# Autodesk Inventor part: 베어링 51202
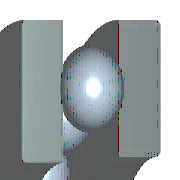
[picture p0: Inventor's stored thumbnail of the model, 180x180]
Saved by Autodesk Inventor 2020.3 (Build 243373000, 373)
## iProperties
Created: 2012-02
Part Number: 베어링 51202
Material: 강철, 연강
Description: 롤링 베어링 - 플랫 뒷면이 있는 스러스트 볼 베어링
Document SubType Name: Modeling
Standard: KS B 2022
Designer: mduedu
Standards Organization: KS
Language: ko-KR
Size Designation: 51202 - 15 x 32 x 12
Categories: <MemberInstance><Categories><Category DisplayName="샤프트 부품" InternalName="7f7aeb1f-a693-4053-b835-cee3144e0d98" Mnemonic="SHFT"><Category DisplayName="베어링" Inter
Density: 1 g/cm^3
Appearance: 진녹색
IsCustomPart: 1
Author: mduedu
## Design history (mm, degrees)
sketch "스케치1" dims "d3" = 5.28 (= 0.44 x KB)
  geometry: L1 (6, 9.61)-(6, 14.89); L2 (8.64, 12.25)-(3.36, 12.25); L3 (3.6, 16)-(0, 16); L4 (3.6, 7.5)-(0, 7.5); L5 (8.4, 13.35)-(8.4, 16); L6 (8.4, 16)-(12, 16); L7 (12, 16)-(12, 8.5); L8 (12, 8.5)-(8.4, 8.5); L9 (8.4, 8.5)-(8.4, 11.15); L10 (3.6, 16)-(3.6, 13.35); L11 (3.6, 11.15)-(3.6, 7.5); L12 (-1.8, 0)-(10.8, 0) reference; L13 (0, -0.022)-(0, 5.522) reference; 1 further point
  constraints: 22 end point, 5 perpendicular, 2 equal length, 2 midpoint, 2 parallel, 2 point on line, 1 collinear, 10 other
  dimensions: "d8" = 4.8 diameter of L11 L1 (= 0.4 x KB); "d11" = 15 diameter of L4 L12 (= WD); "d12" = 17 diameter of L8 L12 (= KAD1); "d13" = 32 diameter of L3 L12 (= KID1); "d14" = 32 diameter of L6 L12 (= BD); "d15" = 24.5 diameter of point (6, 12.25) L12 (= 0.5 x KID1 + 0.5 x KAD1); "d16" = 6 distance from line of point (6, 12.25) L13 (= 0.5 x KB); "d18" = 12 distance between parallel lines of L7 L13 (= KB)
revolve "본체" stored, may be unused: angle "d9" = 90 deg
revolve "볼" stored, may be unused: angle "d10" = 90 deg
pattern_circular "IDS_ARRAYBALL[SIMPL:T]" dims angle "d2" = 360 deg
body "Solid1"
fillet "모깎기1" dims "d4" = 0.6 (= KRS)
fillet "모깎기2" dims "d5" = 0.6 (= KRS)
other parameters: "WD" = 15 [user parameter; used in 2 equation terms], "KAD1" = 17 [user parameter; used in 3 equation terms], "KID1" = 32 [user parameter; used in 3 equation terms], "BD" = 32 [user parameter; used in 2 equation terms], "KB" = 12 [user parameter; used in 6 equation terms], "KRS" = 0.6 [user parameter; used in 2 equation terms], "d0" = 2.4 (= 0.2 x KB), "d6" = 0, "d7" = 0, "d19" = 0, "d41" = 0, "d42" = 0, "WR" = 7.5 (= 0.5 x WD) [user parameter], "BC" = 1.65e+07 [user parameter], "BBA" = 90 deg [user parameter], "BC0" = 2.7e+07 [user parameter], "BR" = 16 (= 0.5 x BD) [user parameter]
